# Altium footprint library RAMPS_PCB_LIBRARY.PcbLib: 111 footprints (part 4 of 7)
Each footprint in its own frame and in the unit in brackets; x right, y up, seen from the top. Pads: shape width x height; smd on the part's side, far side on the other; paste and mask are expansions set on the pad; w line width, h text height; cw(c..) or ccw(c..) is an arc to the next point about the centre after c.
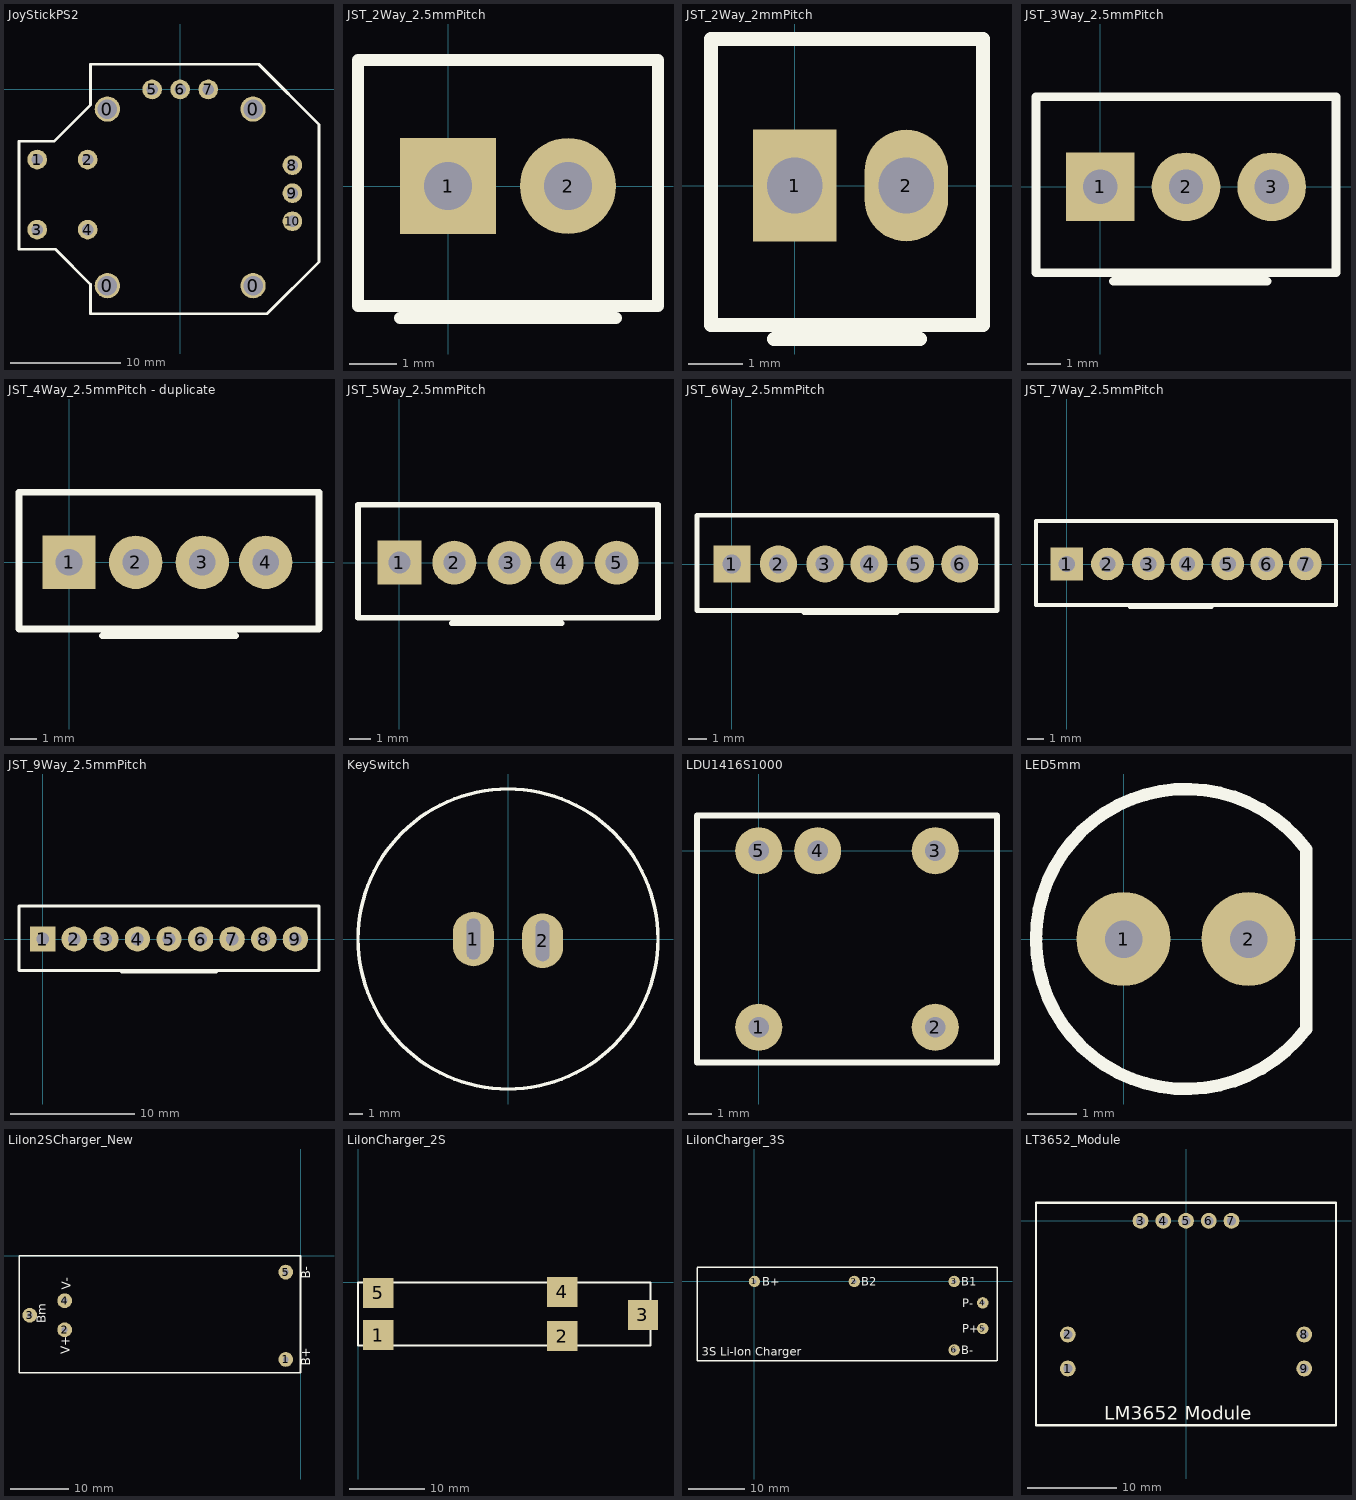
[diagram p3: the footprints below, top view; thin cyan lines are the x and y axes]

## JoyStickPS2 [mil]
pads (14):
  round 90 hole 70: 0(-260,-700) 0(-260,-70) 0(260,-700) 0(260,-70)
  round 70 hole 40: 1(-510,-250) 2(-330,-250) 3(-510,-500) 4(-330,-500) 5(-100,0) 6(0,0) 7(100,0) 8(400,-270) 9(400,-370) 10(400,-470)
Top Overlay:
  lines w10: -575,-570 -575,-185 -450,-185 -320,-55 -320,90 280,90 495,-125 495,-615 310,-800 -320,-800 -320,-695 -445,-570 -575,-570

## JST_2Way_2.5mmPitch [mil]
pads (2):
  rect 80x80 hole 40: 1(0,0)
  round 80 hole 40: 2(100,0)
Top Overlay:
  lines w10: -40,-110 140,-110 ; -75,-100 175,-100 175,105 -75,105 -75,-100

## JST_2Way_2mmPitch [mil]
pads (2):
  rect 60x80 hole 40: 1(0,0)
  oval 60x80 hole 40: 2(80,0)
Top Overlay:
  lines w10: -15,-110 90,-110 ; -60,-100 135,-100 135,105 -60,105 -60,-100

## JST_3Way_2.5mmPitch [mil]
pads (3):
  rect 80x80 hole 40: 1(0,0)
  round 80 hole 40: 2(100,0) 3(200,0)
Top Overlay:
  lines w10: 15,-110 195,-110 ; -75,-100 -75,105 275,105 275,-100 -75,-100

## JST_4Way_2.5mmPitch - duplicate [mil]
pads (4):
  rect 80x80 hole 40: 1(0,0)
  round 80 hole 40: 2(100,0) 3(200,0) 4(295,0)
Top Overlay:
  lines w10: 50,-110 250,-110 ; -75,-100 375,-100 375,105 -75,105 -75,-100

## JST_5Way_2.5mmPitch [mil]
pads (5):
  rect 80x80 hole 40: 1(0,0)
  round 80 hole 40: 2(100,0) 3(200,0) 4(295,0) 5(395,0)
Top Overlay:
  lines w10: 95,-110 295,-110 ; -75,-100 -75,105 470,105 470,-100 -75,-100

## JST_6Way_2.5mmPitch [mil]
pads (6):
  rect 80x80 hole 40: 1(0,0)
  round 80 hole 40: 2(100,0) 3(200,0) 4(295,0) 5(395,0) 6(490,0)
Top Overlay:
  lines w10: 155,-105 355,-105 ; -75,-100 570,-100 570,105 -75,105 -75,-100

## JST_7Way_2.5mmPitch [mil]
pads (7):
  rect 80x80 hole 40: 1(0,0)
  round 80 hole 40: 2(100,0) 3(200,0) 4(295,0) 5(395,0) 6(490,0) 7(585,0)
Top Overlay:
  lines w10: 155,-105 355,-105 ; -75,-100 660,-100 660,105 -75,105 -75,-100

## JST_9Way_2.5mmPitch [mil]
pads (9):
  rect 80x80 hole 40: 1(0,0)
  round 80 hole 40: 2(100,0) 3(200,0) 4(300,0) 5(400,0) 6(500,0) 7(600,0) 8(700,0) 9(800,0)
Top Overlay:
  lines w10: 250,-105 550,-105 ; -75,-100 875,-100 875,105 -75,105 -75,-100

## KeySwitch [mm]
pads (2):
  oval 3x4 hole 1 slot 3 at 90 deg: 1(-2.54,0) 2(2.54,-0.127)
Top Overlay:
  circle w0.254: c0,0 r11

## LDU1416S1000 [mil]
pads (5):
  round 80 hole 35: 1(0,-300) 2(300,-300) 3(300,0) 4(100,0) 5(0,0)
Top Overlay:
  lines w10: -105,-360 405,-360 405,60 -105,60 -105,-360

## LED5mm [mil]
pads (2):
  round 75 hole 30: 1(0,0) 2(100,0)
Top Overlay:
  lines w10: 146,-72 cw(c50,0) 146,72 146,-72

## LiIon2SCharger_New [mil]
pads (5):
  round 100 hole 40: 1(-100,-700.55) 2(-1596.06,-500) 3(-1832.28,-401.57) 4(-1596.06,-303.15) 5(-100,-110)
Top Overlay:
  lines w10: -1.72,-786.57 -1.72,3.43 ; -1905,-790 0,-790 0,0 -1905,0 -1905,-790
  text "B+" at 65,-745 h60
  text "B-" at 65,-155 h60
  text "Bm" at -1725,-455 h60
  text "V+" at -1560,-665 h60
  text "V-" at -1555,-230 h60

## LiIonCharger_2S [mm]
pads (5):
  rect 4x4 smd: 1(2.667,-6.985) 2(27.051,-7.112) 3(37.719,-4.318) 4(27.051,-1.27) 5(2.667,-1.397)
Top Overlay:
  lines w0.254: 0,-8.382 0,0 38.735,0 38.735,-8.382 0,-8.382

## LiIonCharger_3S [mil]
pads (6):
  round 80 hole 30: 1(0,0) 2(700,0) 3(1400,0) 4(1600,-150) 5(1600,-330) 6(1400,-480)
Top Overlay:
  lines w10: -402.55,-556.28 1697.45,-556.28 ; -402.5,-556.28 -402.5,97.5 ; -400,100 1700,100 1700,-555
  text "B-" at 1450,-510 h60
  text "P+" at 1455,-360 h60
  text "P-" at 1455,-180 h60
  text "B1" at 1450,-30 h60
  text "B2" at 750,-30 h60
  text "B+" at 55,-30 h60
  text "3S Li-Ion Charger" at -370,-520.01 h60

## LT3652_Module [mil]
pads (9):
  round 70 hole 40: 1(-520,-650) 2(-520,-500) 3(-200,0) 4(-100,0) 5(0,0) 6(100,0) 7(200,0) 8(520,-500) 9(520,-650)
Top Overlay:
  lines w10: -660,-900 -660,80 660,80 660,-900 -660,-900
  text "LM3652 Module" at -360,-875 h60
